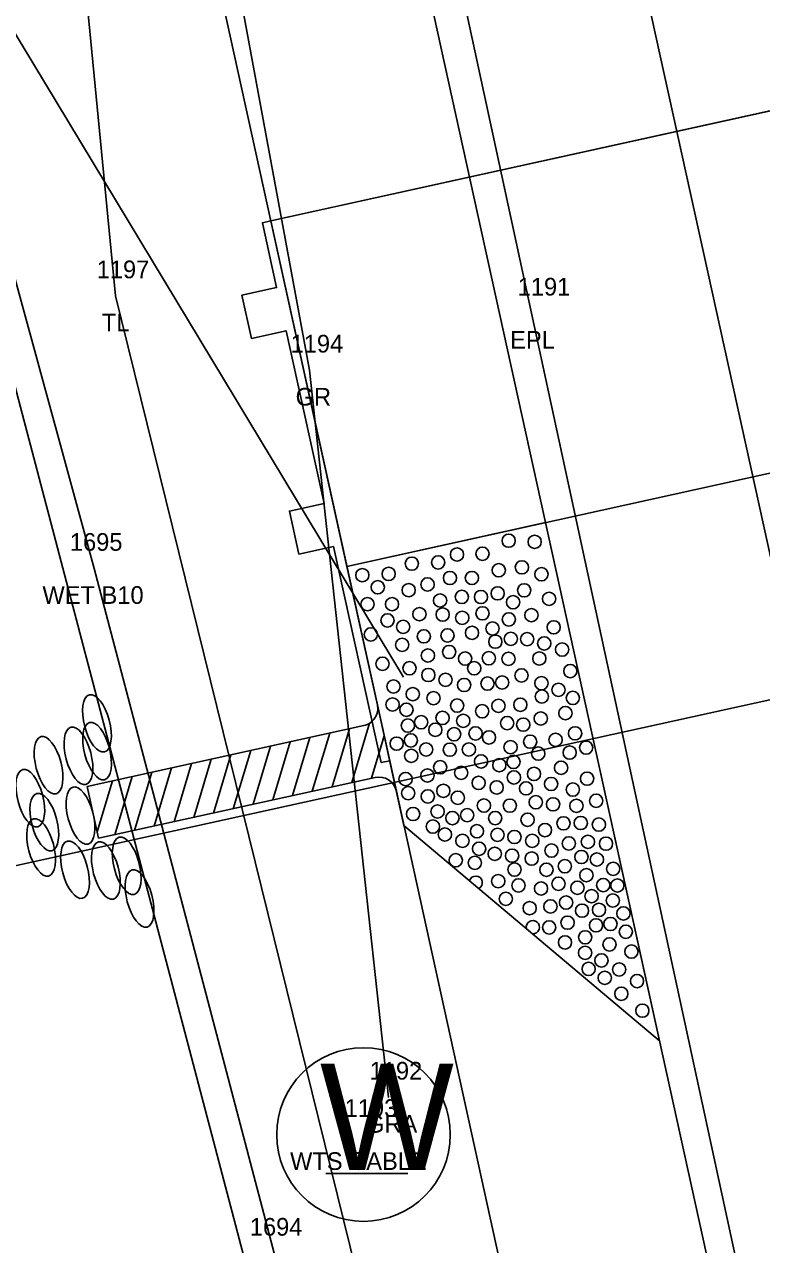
# Model space of a CAD drawing. Extents: x 2522090 to 2524658, y 882711 to 887512.
# Drawn here: x 2523766.8 to 2523808.5, y 884993.3 to 885062.2 of the extents above; entities that cross this region are included whole.
import ezdxf

# ---------------------------------------------------------------- set-up
doc = ezdxf.new("R2010")
doc.units = 0
for name, color, linetype in [('RD_EV_JurisArea', 7, 'Continuous'), ('RD_EX_GuardRail', 7, 'Continuous'), ('RD_EX_GuardRail_txCode', 7, 'Continuous'), ('RD_EX_H2O', 7, 'Continuous'), ('RD_EX_H2O_WetLd_txCode', 7, 'Continuous'), ('RD_EX_Road', 7, 'Continuous'), ('RD_EX_Road_txCode', 7, 'Continuous'), ('RD_EX_UT', 7, 'Continuous'), ('RD_EX_UT_txCode', 7, 'Continuous'), ('RD_EX_VEG', 7, 'Continuous'), ('RD_EX_VEG_txCode', 7, 'Continuous'), ('RD_HC_Cl', 7, 'Continuous'), ('RD_PD_Bridge', 7, 'Continuous'), ('RD_PD_Final_TrvlWay', 7, 'Continuous'), ('RD_PD_GR', 7, 'Continuous'), ('RD_PD_PatLn5', 7, 'Continuous'), ('RD_PD_PatLn6', 7, 'Continuous'), ('RD_PD_PaveShd', 7, 'Continuous'), ('RD_SMD_Locator', 7, 'Continuous')]:
    doc.layers.add(name, color=color, linetype=linetype)

# ---------------------------------------------------------------- blocks, each defined once
blk = doc.blocks.new('TBC1')
at = {"layer": 'RD_PD_GR'}
blk.add_lwpolyline([(12.5, 2.5), (15, 2.5), (15, 0.492), (25, 0.492), (25, 2.5), (27.5, 2.5), (27.5, 0.492), (31.25, 0.492), (31.25, 0), (0, 0), (0, 0.492), (12.5, 0.492)], close=True, dxfattribs=at)

msp = doc.modelspace()

# ---------------------------------------------------------------- linework, layer by layer
at = {"layer": 'RD_EV_JurisArea'}
msp.add_lwpolyline([(2523827.748, 884469.643), (2523867.429, 884517.673), (2523885.95, 884534.838), (2523882.771, 884582.718), (2523847.739, 884736.424), (2523822.93, 884833.786), (2523804.257, 884914.891), (2523780.91, 884992.763), (2523770.735, 885031.476), (2523760.496, 885068.896)], dxfattribs=at)
at = {"layer": 'RD_EX_GuardRail'}
msp.add_lwpolyline([(2523787.377, 885001.584), (2523782.908, 885042.685), (2523776.151, 885079.302)], dxfattribs=at)
at = {"layer": 'RD_EX_H2O'}
msp.add_lwpolyline([(2523792.732, 884941.121), (2523763.674, 885051.555), (2523756.264, 885062.719), (2523770.471, 885094.548), (2523817.567, 885105.706), (2523827.825, 885105.996)], dxfattribs=at)
at = {"layer": 'RD_EX_Road'}
for p, q in [((2523795.465, 885045.906), (2523788.047, 885080.306)), ((2523816.996, 884946.299), (2523795.465, 885045.906))]:
    msp.add_line(p, q, dxfattribs=at)
at = {"layer": 'RD_EX_UT'}
msp.add_line((2523783.84, 884997.269), (2523788.469, 884997.269), dxfattribs=at)
msp.add_circle((2523785.968, 884999.477), 4.908, dxfattribs=at)
at = {"layer": 'RD_EX_VEG'}
msp.add_lwpolyline([(2523800.231, 884418.22), (2523892.245, 884498.974), (2523844.575, 884752.813), (2523771.945, 885046.883), (2523769.056, 885076.621)], dxfattribs=at)
at = {"layer": 'RD_HC_Cl'}
msp.add_line((2523641.165, 885794.201), (2524197.759, 883266.557), dxfattribs=at)
at = {"layer": 'RD_PD_Bridge'}
for p, q in [((2523780.729, 885051.128), (2523826.629, 885061.235)), ((2523830.93, 885041.703), (2523785.03, 885031.596))]:
    msp.add_line(p, q, dxfattribs=at)
for points in [[(2523748.471, 885197.618), (2523785.03, 885031.596)], [(2523780.729, 885051.128), (2523826.629, 885061.235)]]:
    msp.add_lwpolyline(points, dxfattribs=at)
at = {"layer": 'RD_PD_Final_TrvlWay'}
msp.add_line((2523698.951, 885475.979), (2524014, 884045.256), dxfattribs=at)
at = {"layer": 'RD_PD_GR'}
msp.add_line((2523854.115, 884717.862), (2523787.449, 885020.609), dxfattribs=at)
at = {"layer": 'RD_PD_PatLn5'}
msp.add_line((2523888.797, 885041.644), (2523732.541, 885007.236), dxfattribs=at)
at = {"layer": 'RD_PD_PatLn6'}
msp.add_line((2523705.543, 885162.303), (2523788.232, 885025.327), dxfattribs=at)
at = {"layer": 'RD_PD_PaveShd'}
for p, q in [((2523796.261, 885034.069), (2523785.03, 885031.596)), ((2523796.261, 885034.069), (2523802.712, 885004.771)), ((2523786.965, 885022.806), (2523785.03, 885031.596)), ((2523785.03, 885031.596), (2523786.965, 885022.806)), ((2523770.341, 885019.155), (2523785.988, 885022.592)), ((2523786.312, 885022.726), (2523785.308, 885019.371)), ((2523786.965, 885022.806), (2523787.611, 885019.877)), ((2523782.94, 885021.922), (2523781.956, 885018.635)), ((2523782.94, 885021.922), (2523781.956, 885018.635)), ((2523784.058, 885022.168), (2523783.074, 885018.88)), ((2523784.058, 885022.168), (2523783.074, 885018.88)), ((2523785.175, 885022.413), (2523784.191, 885019.125)), ((2523785.175, 885022.413), (2523784.191, 885019.125)), ((2523787.141, 885022.007), (2523786.426, 885019.616)), ((2523787.179, 885021.836), (2523787.179, 885021.836)), ((2523779.589, 885021.186), (2523778.605, 885017.898)), ((2523779.589, 885021.186), (2523778.605, 885017.898)), ((2523780.706, 885021.431), (2523779.722, 885018.144)), ((2523780.706, 885021.431), (2523779.722, 885018.144)), ((2523781.823, 885021.677), (2523780.839, 885018.389)), ((2523781.823, 885021.677), (2523780.839, 885018.389)), ((2523776.237, 885020.45), (2523775.253, 885017.162)), ((2523776.237, 885020.45), (2523775.253, 885017.162)), ((2523777.354, 885020.695), (2523776.37, 885017.407)), ((2523777.354, 885020.695), (2523776.37, 885017.407)), ((2523778.471, 885020.941), (2523777.487, 885017.653)), ((2523778.471, 885020.941), (2523777.487, 885017.653)), ((2523774.002, 885019.959), (2523773.018, 885016.671)), ((2523774.002, 885019.959), (2523773.018, 885016.671)), ((2523775.119, 885020.204), (2523774.135, 885016.917)), ((2523775.119, 885020.204), (2523774.135, 885016.917)), ((2523787.611, 885019.877), (2523788.256, 885016.947)), ((2523770.984, 885016.224), (2523770.341, 885019.155)), ((2523770.984, 885016.224), (2523770.341, 885019.155)), ((2523771.768, 885019.468), (2523770.905, 885016.586)), ((2523771.768, 885019.468), (2523770.905, 885016.586)), ((2523786.634, 885019.662), (2523770.984, 885016.224)), ((2523772.885, 885019.713), (2523771.901, 885016.426)), ((2523772.885, 885019.713), (2523771.901, 885016.426)), ((2523788.256, 885016.947), (2523802.712, 885004.771))]:
    msp.add_line(p, q, dxfattribs=at)
for centre in [(2523794.177, 885033.047), (2523794.177, 885033.047), (2523795.645, 885032.98), (2523795.645, 885032.98), (2523790.191, 885031.82), (2523790.191, 885031.82), (2523791.255, 885032.267), (2523791.255, 885032.267), (2523792.695, 885032.312), (2523792.695, 885032.312), (2523785.901, 885031.098), (2523785.901, 885031.098), (2523787.391, 885031.169), (2523787.391, 885031.169), (2523787.391, 885031.169), (2523788.701, 885031.749), (2523788.701, 885031.749), (2523793.614, 885031.376), (2523793.614, 885031.376), (2523794.925, 885031.542), (2523794.925, 885031.542), (2523796.028, 885031.15), (2523796.028, 885031.15), (2523786.773, 885030.414), (2523789.59, 885030.574), (2523789.59, 885030.574), (2523790.857, 885030.939), (2523790.857, 885030.939), (2523792.098, 885030.94), (2523792.098, 885030.94), (2523788.522, 885030.252), (2523788.522, 885030.252), (2523791.529, 885029.869), (2523791.529, 885029.869), (2523792.61, 885029.863), (2523792.61, 885029.863), (2523793.554, 885030.07), (2523793.554, 885030.07), (2523795.053, 885030.242), (2523795.053, 885030.242), (2523796.459, 885029.76), (2523796.459, 885029.76), (2523786.194, 885029.459), (2523786.194, 885029.459), (2523787.581, 885029.458), (2523787.581, 885029.458), (2523790.297, 885029.666), (2523790.297, 885029.666), (2523794.424, 885029.569), (2523794.424, 885029.569), (2523787.326, 885028.541), (2523787.326, 885028.541), (2523789.128, 885028.892), (2523789.128, 885028.892), (2523790.445, 885028.871), (2523790.445, 885028.871), (2523791.55, 885028.688), (2523791.55, 885028.688), (2523792.699, 885028.941), (2523792.699, 885028.941), (2523794.188, 885028.599), (2523794.188, 885028.599), (2523795.46, 885028.839), (2523795.46, 885028.839), (2523786.385, 885027.748), (2523786.385, 885027.748), (2523788.21, 885028.175), (2523788.21, 885028.175), (2523789.378, 885027.639), (2523789.378, 885027.639), (2523790.717, 885027.693), (2523790.717, 885027.693), (2523792.104, 885027.837), (2523792.104, 885027.837), (2523793.26, 885028.082), (2523796.722, 885028.151), (2523796.722, 885028.151), (2523788.153, 885027.158), (2523788.153, 885027.158), (2523793.423, 885027.339), (2523793.423, 885027.339), (2523794.299, 885027.497), (2523794.299, 885027.497), (2523795.224, 885027.483), (2523795.224, 885027.483), (2523796.188, 885027.242), (2523796.188, 885027.242), (2523789.612, 885026.556), (2523789.612, 885026.556), (2523790.809, 885026.756), (2523790.809, 885026.756), (2523791.71, 885026.383), (2523791.71, 885026.383), (2523793.053, 885026.403), (2523793.053, 885026.403), (2523794.168, 885026.372), (2523794.168, 885026.372), (2523795.909, 885026.389), (2523795.909, 885026.389), (2523797.198, 885026.893), (2523797.198, 885026.893), (2523787.039, 885026.09), (2523787.039, 885026.09), (2523788.569, 885025.835), (2523788.569, 885025.835), (2523792.229, 885025.836), (2523792.229, 885025.836), (2523797.661, 885025.679), (2523797.661, 885025.679), (2523789.633, 885025.454), (2523789.633, 885025.454), (2523790.607, 885025.184), (2523790.607, 885025.184), (2523791.656, 885024.89), (2523791.656, 885024.89), (2523792.982, 885024.969), (2523792.982, 885024.969), (2523793.808, 885025.033), (2523793.808, 885025.033), (2523794.899, 885025.43), (2523794.899, 885025.43), (2523796.028, 885024.989), (2523796.028, 885024.989), (2523787.667, 885024.806), (2523787.667, 885024.806), (2523788.751, 885024.374), (2523788.751, 885024.374), (2523796.051, 885024.238), (2523796.051, 885024.238), (2523796.992, 885024.618), (2523796.992, 885024.618), (2523787.611, 885023.79), (2523787.611, 885023.79), (2523789.924, 885024.147), (2523789.924, 885024.147), (2523791.266, 885023.725), (2523791.266, 885023.725), (2523793.598, 885023.71), (2523793.598, 885023.71), (2523794.837, 885023.774), (2523794.837, 885023.774), (2523797.807, 885024.157), (2523788.393, 885023.493), (2523790.438, 885023.028), (2523790.438, 885023.028), (2523791.609, 885022.864), (2523791.609, 885022.864), (2523792.68, 885023.406), (2523792.68, 885023.406), (2523795.989, 885022.995), (2523795.989, 885022.995), (2523797.383, 885023.302), (2523797.383, 885023.302), (2523788.479, 885022.594), (2523788.479, 885022.594), (2523789.226, 885022.785), (2523789.226, 885022.785), (2523790.029, 885022.359), (2523790.029, 885022.359), (2523792.304, 885022.154), (2523792.304, 885022.154), (2523794.092, 885022.736), (2523794.092, 885022.736), (2523795.002, 885022.647), (2523795.002, 885022.647), (2523797.929, 885022.157), (2523797.929, 885022.157), (2523787.843, 885021.575), (2523787.843, 885021.575), (2523788.643, 885021.759), (2523788.643, 885021.759), (2523791.09, 885022.103), (2523791.09, 885022.103), (2523793.064, 885021.927), (2523793.064, 885021.927), (2523795.39, 885021.686), (2523795.39, 885021.686), (2523796.828, 885021.793), (2523796.828, 885021.793), (2523788.67, 885020.883), (2523788.67, 885020.883), (2523789.509, 885021.243), (2523789.509, 885021.243), (2523790.85, 885021.234), (2523790.85, 885021.234), (2523791.928, 885021.243), (2523791.928, 885021.243), (2523794.284, 885021.376), (2523794.284, 885021.376), (2523795.849, 885021.011), (2523795.849, 885021.011), (2523797.624, 885021.069), (2523797.624, 885021.069), (2523798.556, 885021.349), (2523798.556, 885021.349), (2523790.304, 885020.24), (2523790.304, 885020.24), (2523792.616, 885020.572), (2523792.616, 885020.572), (2523793.648, 885020.356), (2523793.648, 885020.356), (2523794.447, 885020.541), (2523794.447, 885020.541), (2523797.14, 885020.211), (2523797.14, 885020.211), (2523788.348, 885019.57), (2523788.348, 885019.57), (2523789.581, 885019.774), (2523789.581, 885019.774), (2523791.492, 885019.926), (2523791.492, 885019.926), (2523794.474, 885019.665), (2523794.474, 885019.665), (2523795.609, 885019.863), (2523795.609, 885019.863), (2523798.61, 885019.596), (2523798.61, 885019.596), (2523788.496, 885018.775), (2523788.496, 885018.775), (2523790.483, 885018.905), (2523790.483, 885018.905), (2523792.478, 885019.352), (2523792.478, 885019.352), (2523793.498, 885019.099), (2523793.498, 885019.099), (2523795.158, 885019.047), (2523795.158, 885019.047), (2523796.576, 885019.295), (2523796.576, 885019.295), (2523797.805, 885018.979), (2523797.805, 885018.979), (2523789.602, 885018.593), (2523789.602, 885018.593), (2523791.298, 885018.516), (2523791.298, 885018.516), (2523792.778, 885018.074), (2523792.778, 885018.074), (2523794.245, 885018.069), (2523794.245, 885018.069), (2523795.708, 885018.262), (2523795.708, 885018.262), (2523796.687, 885018.145), (2523796.687, 885018.145), (2523798.005, 885018.061), (2523798.005, 885018.061), (2523799.125, 885018.346), (2523799.125, 885018.346), (2523788.769, 885017.598), (2523788.769, 885017.598), (2523790.156, 885017.741), (2523790.156, 885017.741), (2523790.156, 885017.741), (2523790.995, 885017.367), (2523790.995, 885017.367), (2523791.829, 885017.53), (2523791.829, 885017.53), (2523793.414, 885017.367), (2523793.414, 885017.367), (2523789.892, 885016.887), (2523792.384, 885016.62), (2523792.384, 885016.62), (2523795.247, 885017.273), (2523795.247, 885017.273), (2523796.23, 885016.69), (2523796.23, 885016.69), (2523797.274, 885017.07), (2523797.274, 885017.07), (2523798.251, 885017.088), (2523798.251, 885017.088), (2523799.279, 885016.998), (2523799.279, 885016.998), (2523790.572, 885016.439), (2523790.572, 885016.439), (2523791.561, 885016.081), (2523791.561, 885016.081), (2523793.543, 885016.418), (2523793.543, 885016.418), (2523794.5, 885016.298), (2523794.5, 885016.298), (2523795.509, 885016.078), (2523795.509, 885016.078), (2523797.58, 885015.934), (2523797.58, 885015.934), (2523798.659, 885016.025), (2523798.659, 885016.025), (2523799.679, 885015.921), (2523799.679, 885015.921), (2523792.502, 885015.634), (2523792.502, 885015.634), (2523793.388, 885015.348), (2523793.388, 885015.348), (2523794.369, 885015.241), (2523794.369, 885015.241), (2523796.597, 885015.531), (2523796.597, 885015.531), (2523791.183, 885014.983), (2523792.263, 885014.837), (2523792.263, 885014.837), (2523795.477, 885015.075), (2523795.477, 885015.075), (2523797.351, 885014.644), (2523797.351, 885014.644), (2523798.288, 885015.167), (2523798.288, 885015.167), (2523799.166, 885015.023), (2523799.166, 885015.023), (2523794.506, 885014.456), (2523794.506, 885014.456), (2523796.308, 885014.448), (2523796.308, 885014.448), (2523798.57, 885014.138), (2523798.57, 885014.138), (2523800.085, 885014.5), (2523800.085, 885014.5), (2523793.586, 885013.8), (2523793.586, 885013.8), (2523794.734, 885013.56), (2523794.734, 885013.56), (2523796.006, 885013.387), (2523796.006, 885013.387), (2523796.992, 885013.653), (2523796.992, 885013.653), (2523798.062, 885013.427), (2523798.062, 885013.427), (2523799.526, 885013.58), (2523799.526, 885013.58), (2523800.322, 885013.555), (2523800.322, 885013.555), (2523794.015, 885012.8), (2523797.422, 885012.591), (2523797.422, 885012.591), (2523798.865, 885012.951), (2523798.865, 885012.951), (2523800.068, 885012.709), (2523800.068, 885012.709), (2523795.363, 885012.277), (2523795.363, 885012.277), (2523796.537, 885012.372), (2523796.537, 885012.372), (2523798.324, 885012.132), (2523798.324, 885012.132), (2523799.283, 885012.176), (2523799.283, 885012.176), (2523800.664, 885011.976), (2523800.664, 885011.976), (2523796.466, 885011.188), (2523796.466, 885011.188), (2523797.507, 885011.455), (2523797.507, 885011.455), (2523799.116, 885011.305), (2523799.116, 885011.305), (2523799.93, 885011.38), (2523799.93, 885011.38), (2523798.499, 885010.627), (2523798.499, 885010.627), (2523800.803, 885010.942), (2523800.803, 885010.942), (2523797.362, 885010.34), (2523797.362, 885010.34), (2523798.498, 885009.749), (2523799.88, 885010.226), (2523799.88, 885010.226), (2523801.117, 885009.82), (2523801.117, 885009.82), (2523799.421, 885009.323), (2523799.421, 885009.323), (2523798.698, 885008.84), (2523799.609, 885008.334), (2523799.609, 885008.334), (2523800.425, 885008.81), (2523800.425, 885008.81), (2523801.434, 885008.154), (2523801.434, 885008.154), (2523800.546, 885007.439), (2523800.546, 885007.439), (2523801.736, 885006.481), (2523801.736, 885006.481)]:
    msp.add_circle(centre, 0.375, dxfattribs=at)
for centre, radius, start, end in [((2523785.774, 885023.568), 1, 282.38886, 12.41848), ((2523786.849, 885018.685), 1, 12.41848, 102.38886), ((2523792.314, 885013.712), 0.375, 297.93937, 161.84996), ((2523795.544, 885011.201), 0.375, 266.75217, 193.03716)]:
    msp.add_arc(centre, radius, start, end, dxfattribs=at)
for centre in [(2523770.896, 885022.723), (2523770.896, 885022.723), (2523769.849, 885020.885), (2523769.849, 885020.885), (2523770.903, 885021.151), (2523770.903, 885021.151), (2523768.16, 885020.356), (2523768.16, 885020.356), (2523767.126, 885018.494), (2523767.126, 885018.494), (2523769.968, 885017.507), (2523769.968, 885017.507), (2523767.92, 885017.14), (2523767.92, 885017.14), (2523767.738, 885015.706), (2523767.738, 885015.706), (2523772.578, 885014.672), (2523769.657, 885014.45), (2523769.657, 885014.45), (2523771.402, 885014.404), (2523771.402, 885014.404), (2523773.306, 885012.822)]:
    msp.add_ellipse(centre, major_axis=(0.426, -1.616), ratio=0.429445, dxfattribs=at)
at = {"layer": 'RD_SMD_Locator'}
for centre in [(2523771.945, 885046.883), (2523795.465, 885045.906), (2523782.908, 885042.685), (2523770.735, 885031.476), (2523787.377, 885001.584)]:
    msp.add_circle(centre, 0.001, dxfattribs=at)

# ---------------------------------------------------------------- block references
at = {"layer": 'RD_PD_Bridge', "rotation": 102.41848259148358}
msp.add_blockref('TBC1', (2523787.449, 885020.609), dxfattribs=at)

# ---------------------------------------------------------------- texts
at = {"layer": 'RD_EX_GuardRail_txCode'}
for s, p in [('1194', (2523781.845, 885043.685)), ('GR', (2523782.129, 885040.685)), ('1192', (2523786.314, 885002.584)), ('GRA', (2523786.109, 884999.584))]:
    msp.add_text(s, height=1, dxfattribs=at).set_placement(p)
at = {"layer": 'RD_EX_H2O_WetLd_txCode'}
for s, p in [('1695', (2523769.365, 885032.476)), ('WET B10', (2523767.813, 885029.476)), ('1694', (2523779.54, 884993.763))]:
    msp.add_text(s, height=1, dxfattribs=at).set_placement(p)
at = {"layer": 'RD_EX_Road_txCode'}
for s, p in [('1191', (2523794.686, 885046.906)), ('EPL', (2523794.261, 885043.906))]:
    msp.add_text(s, height=1, dxfattribs=at).set_placement(p)
at = {"layer": 'RD_EX_UT'}
msp.add_text('W', height=6, dxfattribs=at).set_placement((2523783.504, 884997.476))
at = {"layer": 'RD_EX_UT_txCode'}
for s, p in [('1193', (2523784.905, 885000.477)), ('WTS CABLE', (2523781.815, 884997.477))]:
    msp.add_text(s, height=1, dxfattribs=at).set_placement(p)
at = {"layer": 'RD_EX_VEG_txCode'}
for s, p in [('1197', (2523770.882, 885047.883)), ('TL', (2523771.173, 885044.883))]:
    msp.add_text(s, height=1, dxfattribs=at).set_placement(p)

doc.saveas('drawing.dxf')
